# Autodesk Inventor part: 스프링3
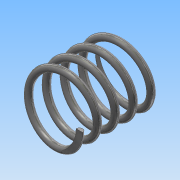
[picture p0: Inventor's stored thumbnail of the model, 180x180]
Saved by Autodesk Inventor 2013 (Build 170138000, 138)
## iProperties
Created: 2016-10
Part Number: 스프링3
Material: 강철, 탄소
Document SubType Name: Modeling
Designer: Administrator
Mass: 4.26122 g
Surface Area: 11.283 cm^2
Volume: 0.541451 cm^3
Density: 7.87 g/cm^3
Author: Administrator
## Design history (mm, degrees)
sketch "스케치1"
  geometry: L1 (0, 0)-(0, 16.67); L2 (0, 16.67)-(25, 16.67); C1 r 1 at (9, 0)
  constraints: 4 end point, 1 centre point, 1 horizontal alignment, 1 perpendicular, 1 vertical
  dimensions: "d0" = 16.66987 distance of L1.start L1.end (derived); "d1" = 25 distance of L1.end L2.end; "d2" = 2 diameter of C1; "d3" = 18 diameter of C1.centre L1
feature "코일1" sketch "스케치1" pitch "d4" = 10; turns "d6" = 5; dims "d5" = 27, "d7" = 0, angle "d8" = 90 deg, angle "d9" = 90 deg, "d10" = 0, "d11" = 0
sketch "스케치2"
  geometry: L1 (16.67, 12)-(0, 12); L2 (0, 12)-(0, -12); L3 (0, -12)-(16.67, -12); L4 (16.67, -12)-(16.67, 12); 2 further points
  constraints: 8 end point, 2 parallel, 1 coincident, 1 horizontal, 1 midpoint, 1 perpendicular
  dimensions: "d12" = 16.66987 distance of L1.start L1.end (derived); "d14" = 24 distance of L3.end L1.start
extrude "돌출1" sketch "스케치2" stored distance "d15" = 0; taper "d16" = 0 deg
node "솔리드1"
